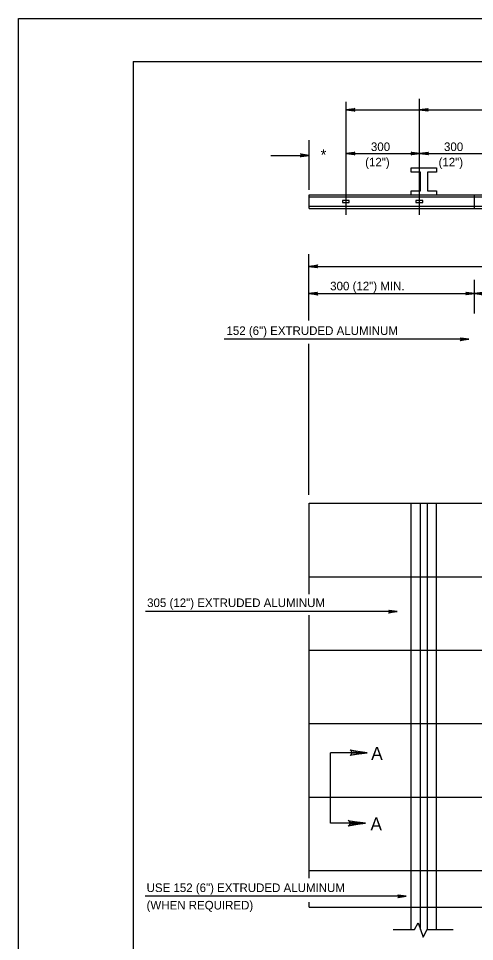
# Model space of a CAD drawing. Extents: x 647822 to 648727, y 298458 to 299646.
# Drawn here: x 647822.3 to 647981.4, y 299323.4 to 299645.6 of the extents above; entities that cross this region are included whole.
import ezdxf

# ---------------------------------------------------------------- set-up
doc = ezdxf.new("R2010")
doc.units = 0
for name, color, linetype in [('1', 7, 'Continuous'), ('2', 7, 'Continuous'), ('3', 7, 'Continuous'), ('XCS-GRID-MIN', 7, 'Continuous')]:
    doc.layers.add(name, color=color, linetype=linetype)

# ---------------------------------------------------------------- blocks, each defined once
blk = doc.blocks.new('RARROW')
at = {"layer": '3'}
blk.add_lwpolyline([(-2.2695, 0.285), (-2.184875, 0.12075), (0, 0), (-2.2695, 0.285), (-2.38575, 0.384625), (0, 0), (-2.183125, -0.108), (-2.262875, -0.2705), (0, 0), (-2.38575, -0.379125), (-2.262875, -0.2705)], dxfattribs=at)

msp = doc.modelspace()

# ---------------------------------------------------------------- linework, layer by layer
at = {"layer": '1'}
for q in [(648648.31, 299630.63), (647862.31, 299066.63)]:
    msp.add_line((647862.31, 299630.63), q, dxfattribs=at)
at = {"layer": '2'}
for p, q in [((647936.63, 299577.1), (647936.63, 299616.48)), ((647962.25, 299577.1), (647962.25, 299617.6)), ((647936.63, 299613.73), (647962.25, 299613.73)), ((647936.63, 299613.73), (647936.63, 299613.73)), ((647962.25, 299613.73), (647987.88, 299613.73)), ((647962.25, 299613.73), (647962.25, 299613.73)), ((647923.75, 299585.85), (647923.75, 299603.1)), ((647910.38, 299597.85), (647923.75, 299597.85)), ((647936.63, 299598.48), (647962.38, 299598.48)), ((647962.38, 299598.48), (647987.88, 299598.48)), ((647959.38, 299591.98), (647959.38, 299593.48)), ((647959.38, 299593.48), (647968.13, 299593.48)), ((647968.13, 299593.48), (647968.13, 299591.98)), ((647962.63, 299591.98), (647959.38, 299591.98)), ((647962.63, 299585.48), (647962.63, 299591.98)), ((647968.13, 299591.98), (647965, 299591.98)), ((647965, 299591.98), (647965, 299585.48)), ((647923.75, 299584.1), (648129, 299584.1)), ((647923.75, 299579.35), (647923.75, 299584.1)), ((647959.38, 299583.98), (647959.38, 299585.48)), ((647959.38, 299585.48), (647962.63, 299585.48)), ((647965, 299585.48), (647968.13, 299585.48)), ((647968.13, 299585.48), (647968.13, 299583.98)), ((647981.38, 299579.35), (647981.38, 299584.1)), ((647923.75, 299583.35), (648129, 299583.35)), ((647937.75, 299582.1), (647935.38, 299582.1)), ((647935.38, 299582.1), (647935.38, 299581.35)), ((647935.38, 299581.35), (647937.75, 299581.35)), ((647937.75, 299581.35), (647937.75, 299582.1)), ((647963.38, 299582.1), (647961, 299582.1)), ((647961, 299582.1), (647961, 299581.35)), ((647961, 299581.35), (647963.38, 299581.35)), ((647963.38, 299581.35), (647963.38, 299582.1)), ((647923.75, 299580.1), (648129, 299580.1)), ((647923.75, 299579.35), (648129, 299579.35)), ((647923.63, 299540.24), (647923.63, 299563.35)), ((647923.63, 299559.1), (648128.88, 299559.1)), ((647981.38, 299542.6), (647981.38, 299554.35)), ((647923.63, 299549.6), (647981.38, 299549.6)), ((647981.38, 299549.6), (648128.88, 299549.6)), ((647979.5, 299533.65), (647894.12, 299533.65)), ((647923.63, 299479.35), (647923.63, 299532.01)), ((647923.75, 299476.48), (648129, 299476.48)), ((647923.75, 299444.73), (647923.75, 299476.48)), ((647959.38, 299327.62), (647959.38, 299476.48)), ((647962.63, 299327.62), (647962.63, 299476.48)), ((647965, 299327.62), (647965, 299476.48)), ((647968.13, 299327.62), (647968.13, 299476.48)), ((647923.75, 299450.73), (648129, 299450.73)), ((647954.5, 299438.6), (647866.61, 299438.6)), ((647923.75, 299345.54), (647923.75, 299437.35)), ((647923.75, 299425.1), (648129, 299425.1)), ((647923.75, 299399.48), (648129, 299399.48)), ((647931.13, 299364.73), (647931.13, 299389.35)), ((647944, 299389.35), (647931.13, 299389.35)), ((647923.75, 299373.85), (648129, 299373.85)), ((647943.38, 299364.73), (647931.13, 299364.73)), ((647923.75, 299348.23), (648129, 299348.23)), ((647957.63, 299339.21), (647866.51, 299339.21)), ((647923.75, 299335.48), (647923.75, 299337.23)), ((647923.75, 299335.48), (648129, 299335.48)), ((647960.5, 299327.62), (647961.75, 299330)), ((647961.75, 299330), (647963.56, 299325.01)), ((647953, 299327.62), (647960.5, 299327.62)), ((647963.56, 299325.01), (647964.94, 299327.62)), ((647964.94, 299327.62), (647974, 299327.62))]:
    msp.add_line(p, q, dxfattribs=at)
at = {"layer": 'XCS-GRID-MIN'}
msp.add_lwpolyline([(647822.31, 299645.63), (648663.31, 299645.63), (648663.31, 299051.63), (647822.31, 299051.63)], close=True, dxfattribs=at)

# ---------------------------------------------------------------- block references
at = {"layer": '2', "xscale": 1.2574347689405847, "yscale": 1.3092961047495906, "rotation": 180}
for p in [(647936.63, 299613.73), (647962.25, 299613.73), (647936.63, 299598.48), (647962.38, 299598.48), (647923.63, 299559.1), (647923.63, 299549.6), (647981.38, 299549.6)]:
    msp.add_blockref('RARROW', p, dxfattribs=at)
at = {"layer": '2'}
for p, xscale, yscale in [((647923.75, 299597.85), 1.2574347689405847, 1.3092961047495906), ((647962.38, 299598.48), 1.2574347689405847, 1.3092961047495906), ((647981.38, 299549.6), 1.2574347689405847, 1.3092961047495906), ((647979.5, 299533.65), 1.2574347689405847, 1.3092961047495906), ((647954.5, 299438.6), 1.2574347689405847, 1.3092961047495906), ((647944, 299389.35), 2.5148695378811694, 2.618592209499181), ((647943.38, 299364.73), 2.5148695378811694, 2.618592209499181), ((647957.63, 299339.21), 1.2574347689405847, 1.3092961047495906)]:
    msp.add_blockref('RARROW', p, dxfattribs=dict(at, xscale=xscale, yscale=yscale))

# ---------------------------------------------------------------- texts
for s, height, p in [('*', 3.85, (647927.75, 299596.1)), ('300', 3, (647945.29, 299599.35)), ('300', 3, (647970.79, 299599.35)), ('(12")', 3, (647943.27, 299593.98)), ('(12")', 3, (647968.89, 299593.98)), ('300 (12") MIN.', 3, (647931.08, 299550.73)), ('152 (6") EXTRUDED ALUMINUM', 3, (647894.89, 299535.15)), ('305 (12") EXTRUDED ALUMINUM', 3, (647867.21, 299440.18)), ('A', 4.5, (647945.38, 299386.85)), ('A', 4.5, (647945.13, 299362.23)), ('USE 152 (6") EXTRUDED ALUMINUM', 3, (647867.02, 299340.71)), ('(WHEN REQUIRED)', 3, (647867.01, 299334.62))]:
    msp.add_text(s, height=height, dxfattribs=at).set_placement(p)

doc.saveas('drawing.dxf')
